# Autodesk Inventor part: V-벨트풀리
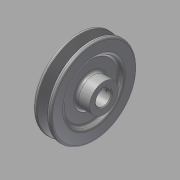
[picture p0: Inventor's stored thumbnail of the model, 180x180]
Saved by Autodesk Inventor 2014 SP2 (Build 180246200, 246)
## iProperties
Created: 2015-09
Part Number: V-벨트풀리
Material: 강철, 연강
Document SubType Name: Modeling
Designer: mduedu
Density: 7.86 g/cm^3
Mass: 779.014 g
Surface Area: 277.465 cm^2
Volume: 99.1112 cm^3
Appearance: 강철
Author: mduedu
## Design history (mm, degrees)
sketch "스케치1"
  geometry: L1 (-10, 0)-(10, 0); L2 (-10, 0)-(-10, 48); L3 (-10, 48)-(-5.976, 48); L4 (-5.976, 48)-(-2.154, 35.5); L5 (-2.154, 35.5)-(2.154, 35.5); L6 (2.154, 35.5)-(5.976, 48); L7 (5.976, 48)-(10, 48); L8 (10, 48)-(10, 0); L9 (0, 0)-(0, 35.5); L10 (-10, 43.5)-(10, 43.5); 3 further points
  constraints: 20 end point, 6 point on line, 3 perpendicular, 2 midpoint, 2 parallel, 2 symmetric about line, 1 coincident, 1 collinear, 1 equal length, 1 horizontal, 1 vertical, 1 vertical alignment
  dimensions: "d0" = 20 distance between parallel lines of L8 L2; "d2" = 96 diameter of L3 L1; "d3" = 87 diameter of L10 L1; "d4" = 4.5 distance between parallel lines of L10 L3 (derived); "d5" = 8 distance between parallel lines of L5 L10; "d6" = 9.2 distance of point (4.6, 43.5) point (-4.6, 43.5); "d7" = 34 deg angle of L6 L4
revolve "회전1" sketch "스케치1" stored, may be unused: angle "d8" = 90 deg
sketch "스케치2"
  geometry: C1 r 16 at (0, 0); 1 further point
  constraints: 1 centre point, 1 coincident
  dimensions: "d9" = 32 diameter of C1
extrude "돌출1" join sketch "스케치2" distance "d10" = 11; taper "d11" = 0 deg
fillet "모깎기1" dims "d12" = 1, "d13" = 0.5, "d14" = 2
sketch "스케치3"
  geometry: C1 r 16 at (0, 0) reference; C2 r 32 at (0, 0); 1 further point
  constraints: 1 centre point, 1 coincident
  dimensions: "d15" = 64 diameter of C2
extrude "돌출2" cut sketch "스케치3" distance "d16" = 4; taper "d17" = 0 deg
fillet "모깎기2" dims "d18" = 3
fillet "모깎기3" dims "d19" = 3
fillet "모깎기4" dims "d20" = 3
sketch "스케치4"
  geometry: C1 r 8.5 at (0, 0); 1 further point
  constraints: 1 centre point, 1 coincident
  dimensions: "d21" = 17 diameter of C1
extrude "돌출3" cut sketch "스케치4" stored distance "d22" = 4; taper "d23" = 0 deg
sketch "스케치5"
  geometry: L1 (-2.5, 8.124)-(2.5, 8.124); L2 (2.5, 8.124)-(2.5, 10.8); L3 (2.5, 10.8)-(-2.5, 10.8); L4 (-2.5, 10.8)-(-2.5, 8.124); A1 r 8.5 centre (0, 0) between (-2.5, 8.124) and (2.5, 8.124) reference; 2 further points
  constraints: 8 end point, 3 point on circle, 2 parallel, 1 horizontal, 1 perpendicular, 1 vertical alignment
  dimensions: "d24" = 5 distance of L2.end L3.end; "d26" = 19.3 distance from line of L3 point (0, -8.5)
extrude "돌출4" cut sketch "스케치5" stored distance "d27" = 4; taper "d28" = 0 deg
chamfer "모따기1" distance "d29" = 1; stored, may be unused: second distance "d30" = 2, angle "d31" = 45 deg
node "작업 평면1"
sketch "스케치6"
  geometry: L1 (-11, 16)-(-11, -16) reference; 2 further points
  constraints: 1 horizontal alignment
  dimensions: "d32" = 5 distance from line of point (-6, 0) L1
hole "구멍1" sketch "스케치6" at (-6, 0) diameter "d33" = 3.242; stored, may be unused: countersink angle "d37" = 90 deg, drill point angle "d39" = 118 deg; dims "d34" = 6, "d35" = 4, "d36" = 2, "d38" = 8
node "솔리드1"
mirror "대칭1"
